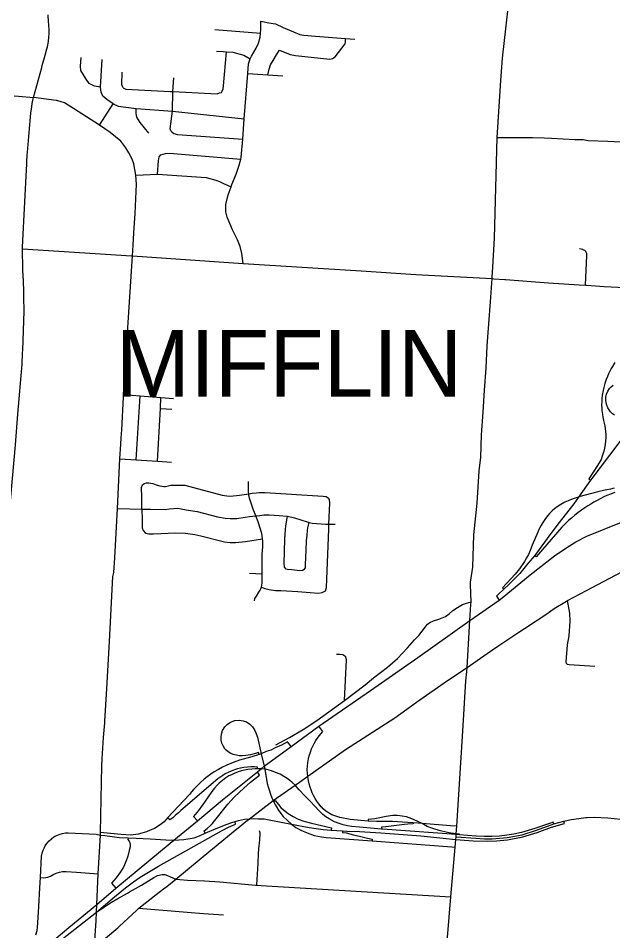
# Model space of a CAD drawing. Extents: x 1755200 to 1902939, y 644115 to 788070.
# Drawn here: x 1846888 to 1854921, y 727307 to 739636 of the extents above; entities that cross this region are included whole.
import ezdxf

# ---------------------------------------------------------------- set-up
doc = ezdxf.new("R2010")
doc.units = 0
for name, color, linetype in [('GM_X_City_Street', 7, 'Continuous'), ('GM_X_County_Road', 7, 'Continuous'), ('GM_X_Interchange_Ramps', 7, 'Continuous'), ('GM_X_Interstate_Route', 7, 'Continuous'), ('GM_X_Township_Road', 7, 'Continuous'), ('GM_X_Township_Text', 7, 'Continuous')]:
    doc.layers.add(name, color=color, linetype=linetype)

msp = doc.modelspace()

# ---------------------------------------------------------------- linework, layer by layer
at = {"layer": 'GM_X_City_Street'}
for points in [[(1853406, 738733), (1853431, 739098), (1853600, 740609)], [(1847276, 739223), (1847283, 739249), (1847295, 739323), (1847303, 739381), (1847305, 739425), (1847305, 739470), (1847300, 739553), (1847298, 739586)], [(1847298, 739586), (1847292, 739680)], [(1849927, 736322), (1849910, 736459), (1849885, 736552), (1849852, 736640), (1849784, 736778), (1849713, 736947), (1849694, 737021), (1849693, 737117), (1849723, 737249), (1849763, 737357), (1849775, 737389), (1849833, 737528), (1849875, 737652), (1849895, 737730), (1849902, 737760), (1849921, 738001), (1849942, 738278), (1849990, 738889), (1850000, 739019), (1850017, 739073), (1850024, 739089), (1850039, 739123), (1850105, 739232), (1850134, 739300), (1850155, 739381), (1850160, 739435), (1850164, 739479), (1850168, 739594)], [(1850168, 739594), (1850274, 739572), (1850365, 739559), (1850469, 739511), (1850608, 739451), (1850691, 739418), (1850749, 739409), (1850903, 739395), (1851308, 739362), (1851435, 739351)], [(1849544, 739484), (1850160, 739435)], [(1850416, 739205), (1850562, 739147), (1850635, 739132), (1851097, 739084), (1851135, 739093), (1851171, 739115), (1851306, 739291), (1851310, 739317), (1851308, 739362)], [(1847205, 738971), (1847212, 738996), (1847252, 739136), (1847276, 739223)], [(1850262, 738870), (1850279, 738949), (1850298, 739005), (1850333, 739066), (1850378, 739140), (1850416, 739205)], [(1847998, 738704), (1847918, 738718), (1847848, 738754), (1847805, 738811), (1847736, 738929), (1847729, 738989), (1847738, 739105)], [(1849568, 739189), (1849656, 739188), (1849700, 739184), (1849788, 739176), (1849868, 739155), (1849938, 739138), (1850024, 739089)], [(1849634, 738633), (1849645, 738651), (1849659, 738683), (1849662, 738723), (1849700, 739184)], [(1847066, 738409), (1847070, 738444), (1847076, 738485), (1847086, 738530), (1847096, 738566), (1847139, 738726), (1847205, 738971)], [(1848169, 738481), (1848084, 738536), (1848033, 738585), (1848007, 738635), (1847998, 738704), (1848023, 739078)], [(1848305, 738696), (1848288, 738736), (1848292, 738905)], [(1849990, 738889), (1850262, 738870), (1850464, 738856)], [(1848963, 738100), (1848949, 738116), (1848943, 738142), (1848974, 738382), (1848978, 738646), (1848991, 738831)], [(1848305, 738696), (1848341, 738679), (1848943, 738648)], [(1848943, 738648), (1848944, 738647), (1848978, 738646), (1849574, 738614), (1849606, 738626), (1849634, 738633)], [(1846831, 738588), (1846892, 738584), (1847096, 738566)], [(1847403, 738524), (1847401, 738524), (1847096, 738566)], [(1848450, 736736), (1848468, 736996), (1848484, 737395), (1848479, 737516), (1848452, 737667), (1848427, 737733), (1848383, 737817), (1848342, 737883), (1848274, 737974), (1848132, 738090), (1847984, 738190), (1847634, 738414), (1847561, 738463), (1847511, 738491), (1847453, 738512), (1847403, 738524)], [(1847984, 738190), (1848169, 738481)], [(1848169, 738481), (1848240, 738446), (1848480, 738417), (1848974, 738382), (1849942, 738278)], [(1847060, 738356), (1847066, 738409)], [(1848653, 738081), (1848536, 738227), (1848489, 738298), (1848480, 738350), (1848480, 738417)], [(1848963, 738100), (1848989, 738079), (1849038, 738064), (1849921, 738001)], [(1853357, 738023), (1853625, 738026), (1853837, 738026), (1853993, 738021), (1854091, 738016), (1854408, 737997), (1854413, 737997)], [(1854413, 737997), (1854519, 737996), (1854589, 737983), (1854855, 737976), (1855203, 737955)], [(1848769, 737530), (1848783, 737708), (1848792, 737762), (1848817, 737792)], [(1848817, 737792), (1848876, 737810), (1848933, 737812), (1849895, 737730)], [(1846995, 737503), (1846995, 737508), (1847003, 737664)], [(1848479, 737516), (1848769, 737530), (1849428, 737482), (1849558, 737448), (1849609, 737429), (1849663, 737404), (1849691, 737390), (1849763, 737357)], [(1848430, 736427), (1848439, 736568), (1848450, 736736)], [(1846954, 736172), (1846952, 736215), (1846949, 736321), (1846947, 736437)], [(1848311, 734518), (1848312, 734551), (1848430, 736427)], [(1848419, 736427), (1848430, 736427), (1849927, 736322), (1851522, 736224), (1852259, 736175)], [(1852999, 731979), (1852998, 732019), (1853029, 732221), (1853046, 732658), (1853090, 733085), (1853117, 733523), (1853138, 733705), (1853149, 734009), (1853172, 734312), (1853188, 734610), (1853209, 734908), (1853225, 735208), (1853248, 735506), (1853270, 735806), (1853290, 736118), (1853291, 736137), (1853300, 736274)], [(1852259, 736175), (1852346, 736169), (1853290, 736118), (1853312, 736116)], [(1853312, 736116), (1853462, 736105), (1853470, 736104)], [(1846647, 732280), (1846651, 732292), (1846677, 732374), (1846705, 732465), (1846723, 732540), (1846738, 732621), (1846760, 732864), (1846812, 733418), (1846853, 733871), (1846882, 734285), (1846943, 734962), (1846948, 735115)], [(1848312, 734551), (1848537, 734534), (1848816, 734513), (1848986, 734500)], [(1848480, 733670), (1848537, 734534)], [(1848772, 733651), (1848809, 734363), (1848816, 734513)], [(1848809, 734363), (1848962, 734354)], [(1848192, 732344), (1848231, 733011), (1848261, 733684), (1848273, 733882)], [(1848261, 733684), (1848480, 733670), (1848772, 733651), (1848958, 733639)], [(1848557, 733001), (1848556, 733066), (1848559, 733200), (1848553, 733261), (1848553, 733295), (1848566, 733331), (1848591, 733352), (1848620, 733361), (1848651, 733361), (1848708, 733349), (1848752, 733334), (1848800, 733320), (1848857, 733310), (1848879, 733311), (1848950, 733329), (1849139, 733326), (1849256, 733294), (1849644, 733194), (1849708, 733185), (1849752, 733180), (1849878, 733193), (1850004, 733211), (1850051, 733218), (1850107, 733224), (1850145, 733228), (1850219, 733228), (1851007, 733179), (1851048, 733172), (1851078, 733150)], [(1850079, 731766), (1850085, 731794), (1850106, 731828), (1850141, 731881), (1850158, 731909), (1850166, 731927), (1850175, 731951), (1850182, 732002), (1850184, 732131), (1850186, 732393), (1850194, 732495), (1850193, 732543), (1850192, 732577), (1850189, 732600), (1850188, 732605), (1850178, 732674), (1850131, 732833), (1850099, 732913), (1850062, 733003), (1850015, 733150), (1850006, 733195), (1850004, 733211), (1849999, 733239), (1850000, 733377)], [(1851038, 731900), (1851046, 731914), (1851053, 731944), (1851060, 732170), (1851083, 732733), (1851086, 732801), (1851096, 733084), (1851092, 733133), (1851078, 733150)], [(1848231, 733011), (1848557, 733001), (1848673, 733005), (1848872, 732997), (1848932, 733006), (1849046, 733016), (1849157, 732994), (1849305, 732972), (1849580, 732899), (1849686, 732881), (1849750, 732875), (1849842, 732879), (1849954, 732895), (1850014, 732904), (1850099, 732913), (1850153, 732919), (1850207, 732926), (1850279, 732928), (1850415, 732917), (1850517, 732909), (1850528, 732907), (1850622, 732885), (1850791, 732831), (1850820, 732825), (1850861, 732816), (1850919, 732810), (1851043, 732802), (1851086, 732801), (1851169, 732799)], [(1848557, 733001), (1848563, 732860), (1848563, 732750), (1848576, 732713), (1848607, 732677), (1848652, 732671), (1848716, 732669), (1849014, 732684), (1849149, 732677), (1849275, 732659), (1849356, 732644), (1849675, 732560), (1849751, 732551), (1849823, 732551), (1849959, 732568), (1850189, 732600)], [(1850750, 732189), (1850728, 732175), (1850692, 732172), (1850584, 732182), (1850524, 732186), (1850506, 732192), (1850486, 732218), (1850480, 732275), (1850490, 732595), (1850496, 732671), (1850504, 732777), (1850528, 732907)], [(1850750, 732189), (1850768, 732210), (1850771, 732252), (1850777, 732451), (1850784, 732573), (1850790, 732653), (1850797, 732713), (1850800, 732751), (1850820, 732825)], [(1850011, 732138), (1850184, 732131)], [(1850175, 731951), (1850220, 731931), (1850280, 731916), (1850364, 731906), (1850438, 731905), (1850668, 731890), (1850834, 731876), (1850945, 731868), (1850994, 731875), (1851038, 731900)], [(1853003, 731713), (1853006, 731749), (1852999, 731979)], [(1852244, 731237), (1852299, 731298), (1852392, 731415), (1852419, 731448), (1852438, 731461), (1852457, 731475), (1852500, 731493), (1852569, 731517), (1852659, 731555), (1852712, 731589), (1852761, 731636), (1852822, 731674), (1852889, 731714), (1852931, 731730), (1853006, 731749)], [(1853727, 731391), (1854028, 731591), (1854130, 731659), (1854295, 731758)], [(1854679, 730877), (1854330, 730900), (1854310, 730904), (1854295, 730919), (1854290, 730940), (1854310, 731169), (1854331, 731290), (1854346, 731491), (1854339, 731600), (1854311, 731768)], [(1851296, 730420), (1851322, 730966), (1851314, 731006), (1851276, 731035), (1851232, 731040), (1851187, 731040)], [(1852430, 723736), (1852474, 725195), (1852643, 726665), (1852732, 727764), (1852792, 728437), (1852801, 728542), (1852804, 728578), (1852806, 728606), (1852806, 728618), (1852813, 728720), (1852894, 730003), (1852934, 730682), (1852947, 730811)], [(1848019, 729535), (1848021, 729630), (1848040, 729920), (1848056, 730118)], [(1847999, 728599), (1848001, 728633), (1848019, 729535)], [(1852804, 728578), (1853073, 728556), (1853190, 728549), (1853292, 728550), (1853496, 728567), (1853696, 728605), (1853889, 728664), (1854125, 728750), (1854262, 728789), (1854360, 728810), (1854461, 728826), (1854559, 728838), (1854574, 728838)], [(1854574, 728838), (1854671, 728840), (1854856, 728833), (1855452, 728768), (1855649, 728737), (1855842, 728686), (1856000, 728628), (1856207, 728530), (1856383, 728441), (1856569, 728364), (1856760, 728312), (1856912, 728280), (1857092, 728262), (1857643, 728227), (1858245, 728167), (1859517, 728067)], [(1847181, 727885), (1847189, 728025), (1847203, 728317), (1847212, 728357), (1847224, 728394), (1847238, 728425), (1847253, 728456), (1847275, 728486), (1847305, 728522), (1847339, 728551), (1847371, 728575), (1847406, 728595), (1847454, 728614), (1847487, 728623), (1847528, 728628), (1847564, 728631), (1847939, 728614), (1847999, 728599)], [(1849511, 728412), (1849840, 728682)], [(1850151, 728546), (1850155, 728610), (1850155, 728632), (1850150, 728658)], [(1847941, 727085), (1847939, 727093), (1847926, 727187), (1847926, 727241), (1847939, 727442), (1847947, 727559), (1847949, 727661), (1847970, 728078), (1847999, 728599)], [(1850111, 727928), (1850129, 728214), (1850136, 728353), (1850144, 728465), (1850146, 728482), (1850151, 728546)], [(1847189, 728025), (1847234, 728022), (1847286, 728029), (1847325, 728045), (1847371, 728073), (1847390, 728080)], [(1847390, 728080), (1847415, 728090), (1847446, 728099), (1847485, 728109), (1847534, 728108), (1847676, 728099), (1847970, 728078)], [(1849070, 728000), (1849176, 727992), (1849403, 727983), (1849613, 727968), (1850093, 727925), (1852732, 727764)], [(1847127, 727253), (1847142, 727312), (1847149, 727355), (1847155, 727413), (1847166, 727634), (1847181, 727885)], [(1848484, 727582), (1848517, 727613), (1848751, 727798), (1848852, 727872), (1848895, 727906)], [(1848517, 727613), (1849170, 727560)], [(1849170, 727560), (1849392, 727542), (1849660, 727522)], [(1847939, 727093), (1848008, 727161), (1848069, 727208), (1848235, 727347), (1848256, 727367)]]:
    msp.add_lwpolyline(points, dxfattribs=at)
at = {"layer": 'GM_X_County_Road'}
for points in [[(1853300, 736274), (1853323, 736665), (1853357, 738023), (1853405, 738721), (1853406, 738733)], [(1847037, 738090), (1847037, 738092), (1847060, 738353), (1847060, 738356)], [(1847009, 737770), (1847010, 737787), (1847016, 737878), (1847037, 738090)], [(1847003, 737664), (1847005, 737715), (1847009, 737770)], [(1846947, 736437), (1846945, 736522), (1846946, 736542), (1846953, 736718), (1846995, 737503)], [(1846945, 736522), (1848419, 736427)], [(1846948, 735115), (1846950, 735152), (1846968, 735680), (1846965, 735867), (1846962, 735963), (1846954, 736172)], [(1853470, 736104), (1854053, 736060), (1854469, 736034)], [(1854469, 736034), (1854553, 736029), (1854570, 736028), (1854804, 736013), (1855269, 735991), (1855489, 735971), (1855679, 735957)], [(1848273, 733882), (1848278, 733969), (1848289, 734076), (1848311, 734518)], [(1848056, 730118), (1848058, 730137), (1848083, 730580), (1848121, 731213), (1848167, 732094), (1848181, 732147), (1848192, 732344)], [(1854295, 731758), (1854311, 731768), (1854568, 731905), (1854872, 732065), (1855146, 732211), (1855353, 732318)], [(1852953, 730863), (1852990, 731499), (1853003, 731713)], [(1852953, 730863), (1853222, 731051), (1853370, 731151), (1853654, 731342), (1853727, 731391)], [(1849840, 728682), (1849881, 728716), (1849962, 728784), (1850011, 728821), (1850333, 729065), (1850628, 729273), (1850687, 729314), (1850799, 729394), (1851310, 729756), (1851975, 730183), (1852270, 730396), (1852689, 730690), (1852953, 730863)], [(1852947, 730811), (1852953, 730863)], [(1848895, 727906), (1849018, 728004), (1849489, 728394), (1849511, 728412)], [(1848363, 727815), (1848392, 727831), (1848553, 727922), (1848722, 728027), (1848771, 728054), (1848832, 728068), (1848868, 728066), (1848905, 728055), (1848944, 728036), (1849018, 728004)], [(1849018, 728004), (1849070, 728000)], [(1847947, 727559), (1848150, 727693), (1848233, 727744), (1848363, 727815)], [(1848256, 727367), (1848484, 727582)]]:
    msp.add_lwpolyline(points, dxfattribs=at)
at = {"layer": 'GM_X_Interchange_Ramps'}
for points in [[(1854951, 734983), (1854917, 734931), (1854901, 734904), (1854882, 734869), (1854862, 734830), (1854848, 734797), (1854831, 734756), (1854813, 734702), (1854798, 734646), (1854789, 734606), (1854778, 734542), (1854774, 734500), (1854771, 734450), (1854770, 734411), (1854772, 734363), (1854774, 734334), (1854780, 734283), (1854786, 734246), (1854795, 734203), (1854806, 734163), (1854814, 734126), (1854819, 734094), (1854824, 734053), (1854826, 734014), (1854826, 733966), (1854824, 733925), (1854819, 733877), (1854810, 733829), (1854800, 733785), (1854788, 733746), (1854778, 733717), (1854762, 733676), (1854715, 733592), (1854599, 733413), (1854622, 733396)], [(1854946, 734275), (1854919, 734293), (1854891, 734320), (1854871, 734344), (1854854, 734372), (1854839, 734410), (1854831, 734440), (1854827, 734477), (1854829, 734517), (1854838, 734557), (1854854, 734597), (1854876, 734632), (1854899, 734658), (1854925, 734680)], [(1855171, 734122), (1854876, 733731), (1854638, 733418), (1854622, 733396), (1854458, 733166), (1854393, 733074), (1854180, 732800), (1854034, 732608), (1853892, 732409), (1853866, 732378), (1853775, 732267), (1853665, 732136), (1853512, 731979), (1853449, 731920), (1853373, 731848), (1853348, 731829), (1853388, 731774)], [(1854941, 733285), (1854890, 733275), (1854840, 733265), (1854794, 733255), (1854717, 733237), (1854653, 733220), (1854531, 733188), (1854479, 733173), (1854458, 733166), (1854428, 733156), (1854371, 733136), (1854319, 733117), (1854275, 733099), (1854218, 733068), (1854169, 733034), (1854135, 733008), (1854104, 732980), (1854068, 732944), (1854026, 732895), (1854003, 732865), (1853974, 732823), (1853947, 732776), (1853924, 732730), (1853908, 732692), (1853830, 732515), (1853804, 732443), (1853781, 732392), (1853756, 732345), (1853728, 732296), (1853660, 732195), (1853602, 732126), (1853432, 731938), (1853449, 731920)], [(1854947, 733228), (1854892, 733207), (1854842, 733186), (1854802, 733168), (1854751, 733143), (1854710, 733121), (1854666, 733097), (1854623, 733072), (1854582, 733046), (1854543, 733020), (1854497, 732988), (1854448, 732952), (1854408, 732920), (1854364, 732883), (1854323, 732848), (1854274, 732801), (1854232, 732758), (1853887, 732361), (1853866, 732378)], [(1850144, 729688), (1850135, 729714), (1850093, 729701), (1850028, 729686), (1849965, 729675), (1849919, 729672), (1849874, 729672), (1849835, 729680), (1849791, 729690), (1849761, 729703), (1849726, 729723), (1849699, 729747), (1849681, 729767), (1849655, 729807), (1849641, 729841), (1849631, 729883), (1849629, 729924), (1849634, 729965), (1849650, 730013), (1849678, 730060), (1849712, 730096), (1849757, 730126), (1849815, 730147), (1849873, 730152), (1849928, 730144), (1849971, 730128), (1850018, 730097), (1850053, 730062), (1850079, 730021), (1850099, 729983), (1850119, 729922), (1850170, 729697), (1850212, 729530), (1850220, 729492), (1850251, 729296), (1850263, 729251), (1850278, 729209), (1850295, 729151), (1850315, 729103), (1850333, 729065), (1850339, 729052), (1850362, 729002), (1850407, 728926), (1850468, 728849), (1850524, 728795), (1850582, 728747), (1850641, 728701), (1850706, 728664), (1850793, 728628), (1850888, 728596), (1850984, 728577), (1851050, 728569), (1851672, 728522), (1852747, 728441), (1852792, 728437)], [(1852813, 728720), (1852730, 728726), (1852345, 728756), (1852223, 728767), (1852079, 728776), (1851944, 728783), (1851730, 728784), (1851617, 728788), (1851375, 728812), (1851235, 728836), (1851126, 728873), (1851045, 728925), (1851009, 728956), (1850988, 728976), (1850983, 728981), (1850950, 729020), (1850922, 729060), (1850902, 729092), (1850878, 729133), (1850860, 729170), (1850844, 729209), (1850831, 729246), (1850817, 729292), (1850808, 729333), (1850799, 729389), (1850799, 729394), (1850795, 729432), (1850794, 729484), (1850796, 729531), (1850801, 729578), (1850810, 729628), (1850819, 729669), (1850835, 729720), (1850851, 729764), (1850867, 729800), (1850886, 729837), (1850909, 729876), (1850933, 729911), (1850955, 729941), (1851003, 729998), (1850951, 730070)], [(1850574, 729796), (1850527, 729860), (1850443, 729816), (1850361, 729777), (1850300, 729749), (1850239, 729727), (1850170, 729697), (1850144, 729688), (1850046, 729658), (1849878, 729613), (1849790, 729581), (1849708, 729545), (1849647, 729517), (1849592, 729488), (1849537, 729454), (1849490, 729423), (1849440, 729387), (1849400, 729354), (1849347, 729307), (1849306, 729267), (1849257, 729214), (1849231, 729183), (1849203, 729148), (1848905, 728834), (1848858, 728781), (1848805, 728739), (1848727, 728689), (1848670, 728665), (1848620, 728644), (1848560, 728627), (1848508, 728611), (1848408, 728600), (1848281, 728606), (1848041, 728629), (1848001, 728633)], [(1850125, 729497), (1850122, 729519), (1850082, 729521), (1850033, 729521), (1849986, 729518), (1849938, 729512), (1849893, 729504), (1849852, 729494), (1849809, 729481), (1849765, 729464), (1849726, 729447), (1849686, 729426), (1849651, 729405), (1849625, 729388), (1849586, 729359), (1849084, 728931), (1849055, 728902), (1849015, 728867), (1848975, 728834), (1848936, 728804), (1848905, 728834)], [(1854125, 728750), (1854117, 728775), (1854067, 728757), (1853869, 728687), (1853687, 728633), (1853586, 728612), (1853490, 728597), (1853390, 728587), (1853289, 728582), (1853189, 728581), (1853074, 728587), (1852850, 728602), (1852806, 728606), (1851809, 728680), (1851797, 728681), (1851499, 728705), (1851395, 728715), (1851335, 728723), (1851279, 728738), (1851223, 728755), (1851163, 728779), (1851089, 728818), (1851045, 728847), (1851005, 728880), (1850955, 728928), (1850892, 728995), (1850834, 729056), (1850761, 729132), (1850686, 729210), (1850628, 729273), (1850590, 729310), (1850556, 729338), (1850522, 729363), (1850475, 729392), (1850428, 729421), (1850362, 729447), (1850309, 729468), (1850246, 729487), (1850220, 729492), (1850172, 729497), (1850125, 729497), (1850090, 729497), (1850045, 729491), (1849990, 729486), (1849944, 729478), (1849903, 729468), (1849861, 729455), (1849804, 729433), (1849769, 729415), (1849733, 729398), (1849692, 729374), (1849647, 729338), (1849604, 729301), (1849577, 729275), (1849540, 729233), (1849503, 729187), (1849405, 729044), (1849323, 728931), (1849256, 728853), (1849309, 728792)], [(1849412, 728624), (1849399, 728657), (1849443, 728689), (1849487, 728730), (1849514, 728758), (1849544, 728795), (1849721, 729017), (1849805, 729110), (1849872, 729177), (1849936, 729235), (1850028, 729315), (1850146, 729411), (1850119, 729454)], [(1850339, 729052), (1850359, 729068), (1850377, 729045), (1850403, 729015), (1850438, 728974), (1850472, 728940), (1850535, 728891), (1850602, 728849), (1850671, 728815), (1850747, 728787), (1850851, 728762), (1851119, 728699), (1851114, 728668)], [(1852850, 728602), (1852850, 728613), (1852806, 728618), (1852733, 728626), (1852687, 728633), (1852577, 728661), (1852489, 728689), (1852414, 728717), (1852345, 728756), (1852280, 728789), (1852207, 728821), (1852136, 728845), (1852074, 728857), (1852007, 728865), (1851948, 728864), (1851859, 728853), (1851704, 728821), (1851618, 728811), (1851617, 728788)], [(1847017, 726856), (1847056, 726822), (1847206, 726960), (1847487, 727199), (1847947, 727559), (1848189, 727765), (1848337, 727889), (1848446, 727968), (1848537, 728032), (1848783, 728180), (1849633, 728657), (1849730, 728707), (1849824, 728748), (1849817, 728783)], [(1847999, 728599), (1848057, 728594), (1848255, 728567), (1848372, 728562), (1848482, 728560), (1848672, 728549), (1848883, 728536), (1848989, 728532), (1849126, 728538), (1849266, 728564), (1849337, 728590), (1849412, 728624), (1849561, 728687), (1849709, 728748), (1849773, 728770), (1849817, 728783), (1849866, 728795), (1849946, 728814), (1850011, 728821), (1850073, 728825), (1850132, 728821), (1850212, 728818), (1850301, 728801), (1850582, 728747), (1850818, 728703), (1851010, 728675), (1851114, 728668), (1851271, 728658), (1851327, 728654), (1851501, 728646), (1851785, 728628), (1852329, 728589), (1852801, 728542), (1853037, 728524), (1853222, 728516), (1853352, 728521), (1853500, 728535), (1853705, 728574), (1853901, 728636), (1854091, 728705), (1854270, 728758), (1854262, 728789)], [(1852223, 728767), (1852224, 728752), (1852151, 728746), (1852108, 728743), (1851853, 728710), (1851798, 728705), (1851797, 728681)], [(1851271, 728658), (1851269, 728636), (1851321, 728628), (1851419, 728605), (1851517, 728581), (1851609, 728558), (1851672, 728543), (1851672, 728522)], [(1848372, 728562), (1848371, 728538), (1848388, 728516), (1848397, 728494), (1848401, 728473), (1848401, 728441), (1848386, 728391), (1848368, 728317), (1848348, 728250), (1848311, 728165), (1848270, 728102), (1848212, 728024), (1848148, 727949), (1848206, 727882)]]:
    msp.add_lwpolyline(points, dxfattribs=at)
at = {"layer": 'GM_X_Interstate_Route'}
for points in [[(1853388, 731774), (1853425, 731803), (1853807, 732118), (1854135, 732374), (1854285, 732478), (1854422, 732562), (1854572, 732637), (1855062, 732836)], [(1848941, 728491), (1848989, 728532), (1849309, 728792), (1849646, 729077), (1850119, 729454), (1850172, 729497), (1850212, 729530), (1850574, 729796), (1850951, 730070), (1851648, 730551), (1852289, 730997), (1852990, 731499), (1853388, 731774)], [(1847949, 727661), (1848206, 727882), (1848941, 728491)], [(1846550, 726198), (1846640, 726331), (1846846, 726638), (1846941, 726770), (1847017, 726856), (1847093, 726939), (1847187, 727026), (1847315, 727137), (1847572, 727350), (1847949, 727661)]]:
    msp.add_lwpolyline(points, dxfattribs=at)
at = {"layer": 'GM_X_Township_Road'}
for points in [[(1854553, 736029), (1854571, 736429), (1854571, 736440), (1854569, 736452), (1854566, 736464), (1854561, 736474), (1854556, 736482), (1854551, 736488), (1854542, 736496), (1854532, 736502), (1854522, 736507), (1854515, 736510), (1854471, 736521)], [(1850369, 729821), (1850555, 729920), (1850739, 730026), (1850923, 730148), (1851296, 730420), (1851574, 730630), (1851690, 730726), (1851876, 730867), (1852012, 730985), (1852149, 731131), (1852244, 731237)]]:
    msp.add_lwpolyline(points, dxfattribs=at)

# ---------------------------------------------------------------- texts
at = {"layer": 'GM_X_Township_Text'}
msp.add_text('MIFFLIN', height=900, rotation=0, dxfattribs=at).set_placement((1848207, 734522))

doc.saveas('drawing.dxf')
